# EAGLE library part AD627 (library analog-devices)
Micropower, Single- and Dual-Supply, Rail-to-Rail Instrumentation Amplifier Source: http://www.analog.com/static/imported-files/data_sheets/AD627.pdf
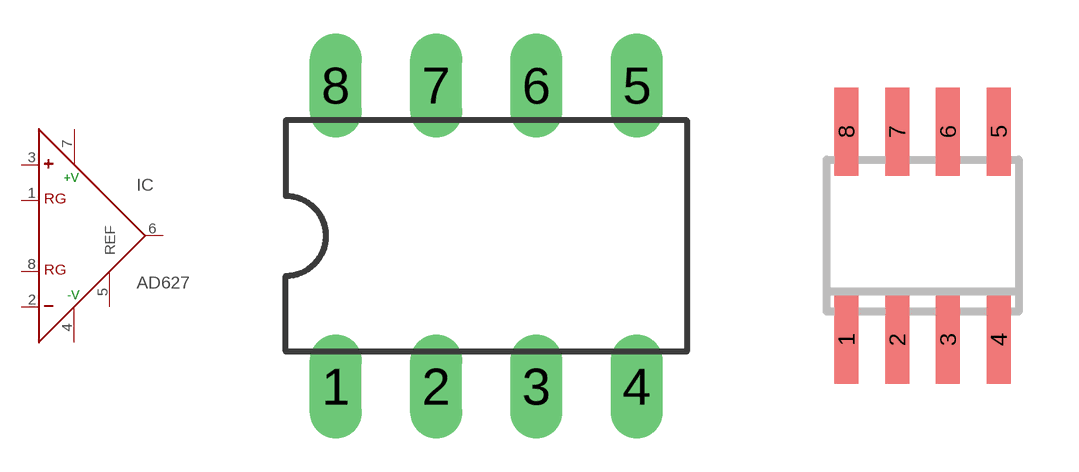
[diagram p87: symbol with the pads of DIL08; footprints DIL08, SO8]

Designator prefix IC

## AD627N (MF: ALTERA CORPORATION; MPN: AD627BNZ; OC_FARNELL: 1438354; OC_NEWARK: 59K4418)  [DIL08]
1  RG  pas
2  -  in
3  +  in
4  -V  pwr
5  REF  pas
6  OUT  out
7  +V  pwr
8  RG  pas

## AD627R (MPN: AD627AR; OC_FARNELL: 1438354; OC_NEWARK: 09B5402)  [SO8]
Pads as for DIL08

## Footprint DIL08 (pad centres in mm)
Dual In Line Package
drill 0.813 long: 1 -3.81,-3.81; 2 -1.27,-3.81; 3 1.27,-3.81; 4 3.81,-3.81; 5 3.81,3.81; 6 1.27,3.81; 7 -1.27,3.81; 8 -3.81,3.81

## Footprint SO8 (pad centres in mm)
8-Lead Small Outline IC (SO-8) Source: http://www.analog.com/UploadedFiles/Data_Sheets/703465986AD8611_2_0.pdf
smd 0.6 x 2.2: 1 -1.905,-2.6; 2 -0.635,-2.6; 3 0.635,-2.6; 4 1.905,-2.6; 5 1.905,2.6; 6 0.635,2.6; 7 -0.635,2.6; 8 -1.905,2.6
